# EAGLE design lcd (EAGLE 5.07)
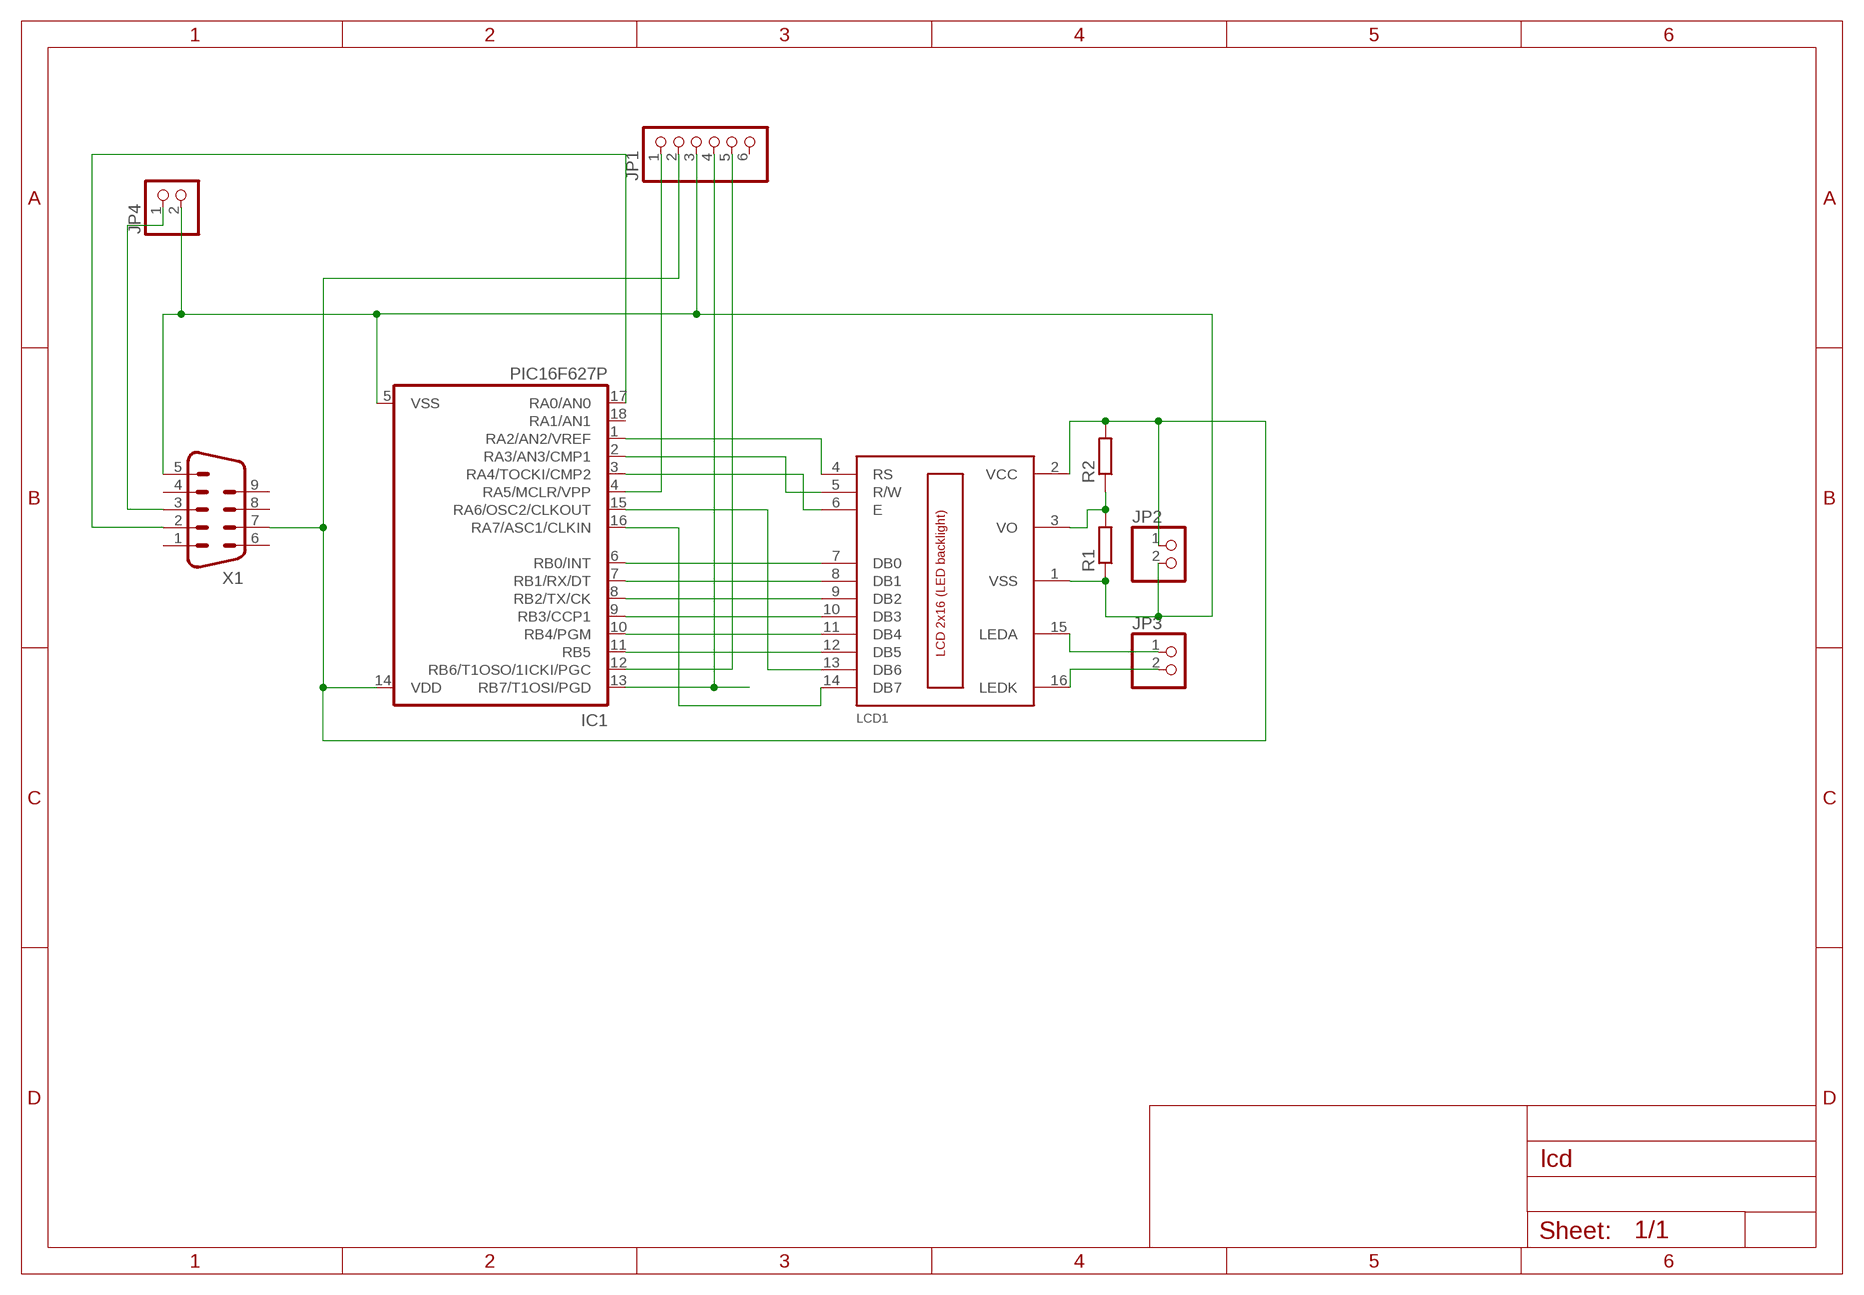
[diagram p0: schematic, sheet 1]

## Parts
IC1  PIC16F627P  [DIL18]
JP1  PINHD-1X6  [1X06]
JP2  PINHD-1X2  [1X02]
JP3  PINHD-1X2  [1X02]
JP4  PINHD-1X2  [1X02]
LCD1  LCD_2X16  [HY-1602F]
R1  R-EU_0204/5  [0204/5]
R2  R-EU_0204/2V  [0204V]
X1  M09HP  [M09HP]

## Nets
N$1: IC1.4(RA5/MCLR/VPP) JP1.1
N$2: IC1.12(RB6/T1OSO/1ICKI/PGC) JP1.5
N$3: IC1.13(RB7/T1OSI/PGD) JP1.4
N$4: IC1.15(RA6/OSC2/CLKOUT) LCD1.13(DB6)
N$5: IC1.16(RA7/ASC1/CLKIN) LCD1.14(DB7)
N$6: IC1.11(RB5) LCD1.12(DB5)
N$7: IC1.10(RB4/PGM) LCD1.11(DB4)
N$8: IC1.9(RB3/CCP1) LCD1.10(DB3)
N$9: IC1.8(RB2/TX/CK) LCD1.9(DB2)
N$10: IC1.7(RB1/RX/DT) LCD1.8(DB1)
N$11: IC1.6(RB0/INT) LCD1.7(DB0)
N$12: IC1.3(RA4/TOCKI/CMP2) LCD1.6(E)
N$13: IC1.1(RA2/AN2/VREF) LCD1.4(RS)
N$14: IC1.2(RA3/AN3/CMP1) LCD1.5(R/W)
N$15: JP3.2 LCD1.16(LEDK)
N$16: JP3.1 LCD1.15(LEDA)
N$18: JP4.1 X1.3
N$19: LCD1.3(VO) R1.2 R2.1
N$20: IC1.17(RA0/AN0) X1.2
VDD: IC1.14(VDD) JP1.2 JP2.1 LCD1.2(VCC) R2.2 X1.7
VSS: IC1.5(VSS) JP1.3 JP2.2 JP4.2 LCD1.1(VSS) R1.1 X1.5
Unconnected: IC1.18(RA1/AN1) JP1.6 X1.1 X1.4 X1.6 X1.8 X1.9

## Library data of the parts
IC1 = microchip:PIC16*F62: FLASH-Based 8-Bit CMOS Microcontroller Source: http://ww1.microchip.com/downloads/en/DeviceDoc/40300C.pdf
JP1 = pinhead:PINHD-1X6: PIN HEADER
JP2 JP3 = pinhead:PINHD-1X2: PIN HEADER
JP4 = pinhead(2):PINHD-1X2: PIN HEADER
LCD1 = lcd_2x16_led_backlight:LCD_2X16
R1 R2 = rcl:R-EU_: RESISTOR, European symbol
X1 = con-subd:M09: SUB-D

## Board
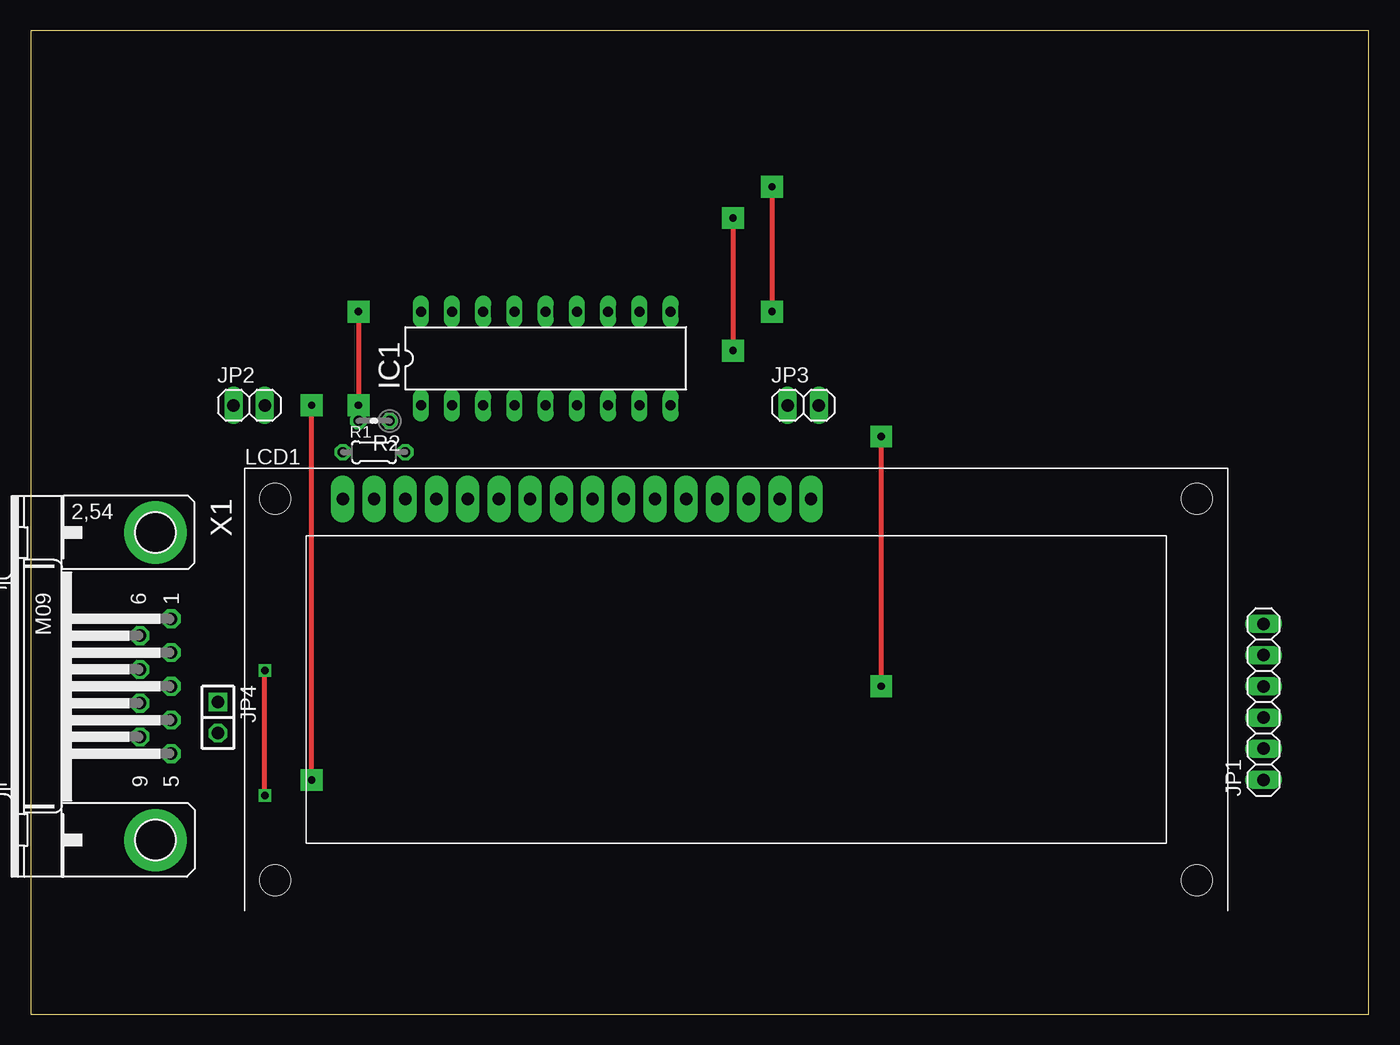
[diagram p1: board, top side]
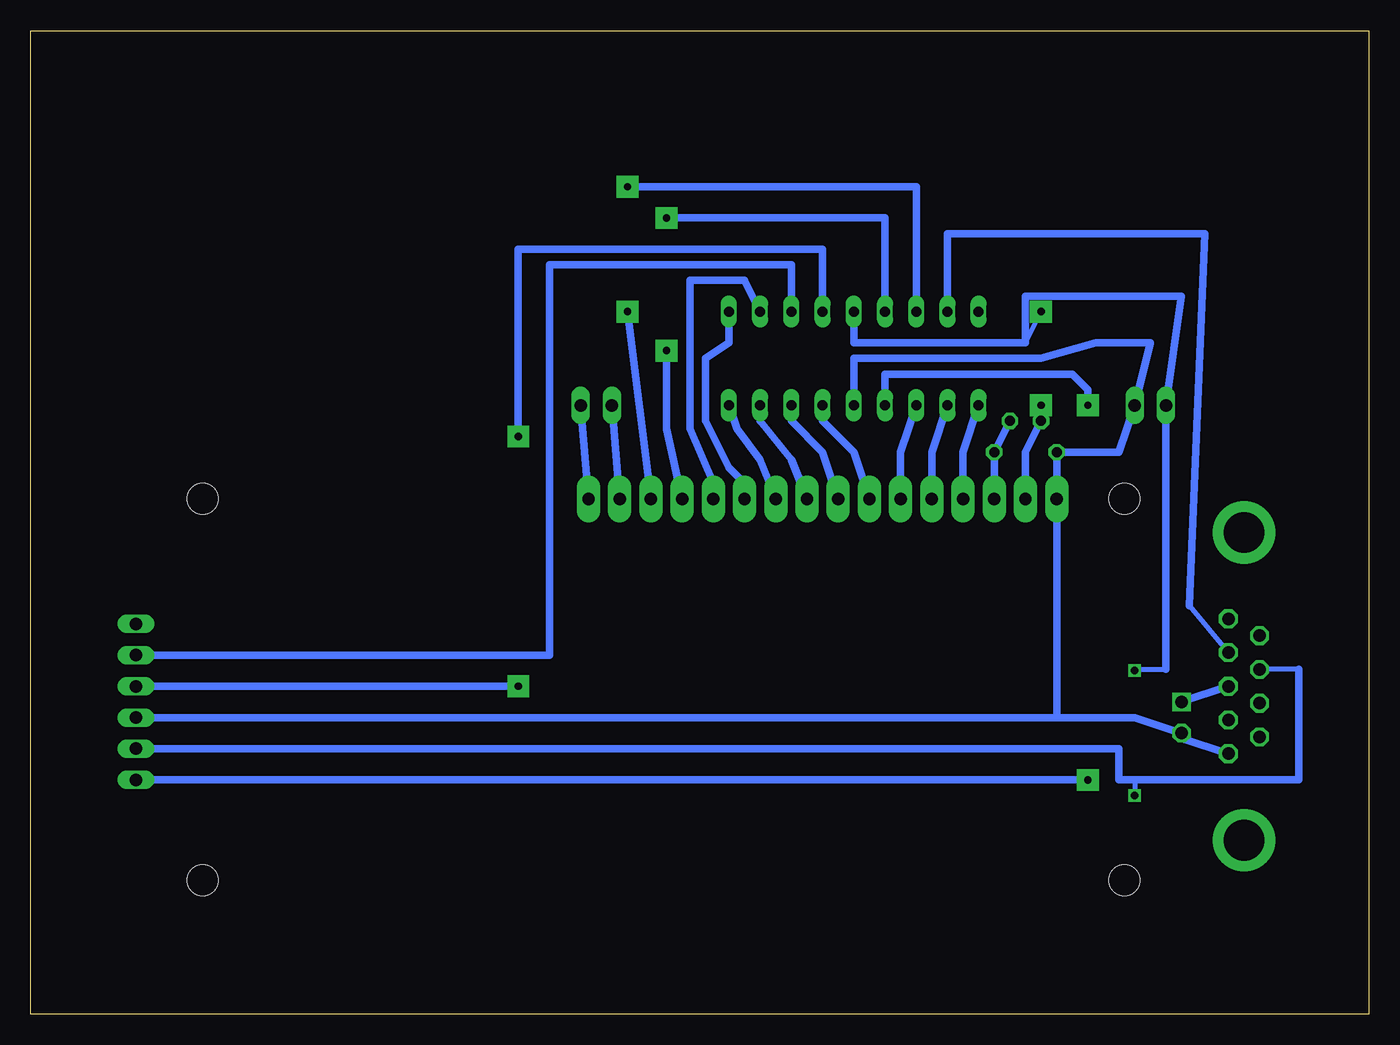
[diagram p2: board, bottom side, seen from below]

Size 108.89 x 80 mm. Coordinates in mm from the lower left corner, seen from the top.
Outline: 0,0 108.89,0 108.89,80 0,80 0,0
Copper layers (1*16): Top 0.035mm / dielectric 1.5mm / Bottom 0.035mm
Design rules "default": minimum track width 10mil, minimum drill 24mil, track to track 8mil, track to pad 8mil, pad to pad 8mil, via to via 8mil, smd to smd 8mil, copper to edge 40mil, drill to drill 8mil, minimum pad ring 10mil, minimum via ring 8mil, stop-mask expansion 4mil, vias tented up to drill 0mil, thermal gap 10mil

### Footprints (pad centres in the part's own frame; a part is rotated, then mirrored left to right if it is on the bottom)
DIL18 = drill 0.813 long: 1 -10.16,-3.81; 2 -7.62,-3.81; 3 -5.08,-3.81; 4 -2.54,-3.81; 5 0,-3.81; 6 2.54,-3.81; 7 5.08,-3.81; 8 7.62,-3.81; 9 10.16,-3.81; 10 10.16,3.81; 11 7.62,3.81; 12 5.08,3.81; 13 2.54,3.81; 14 0,3.81; 15 -2.54,3.81; 16 -5.08,3.81; 17 -7.62,3.81; 18 -10.16,3.81
1X06 = drill 1.016 long: 1 -6.35,0; 2 -3.81,0; 3 -1.27,0; 4 1.27,0; 5 3.81,0; 6 6.35,0
1X02 = drill 1.016 long: 1 -1.27,0; 2 1.27,0
1X02' = drill 1.016 square: 1 -1.27,0 | drill 1.016 octagon: 2 1.27,0
HY-1602F = drill 1 pad 1.93 long: 1 2.54,0; 2 5.08,0; 3 7.62,0; 4 10.16,0; 5 12.7,0; 6 15.24,0; 7 17.78,0; 8 20.32,0; 9 22.86,0; 10 25.4,0; 11 27.94,0; 12 30.48,0; 13 33.02,0; 14 35.56,0; 15 38.1,0; 16 40.64,0 | hole 2.5: -2.96,0; 72.04,0; -2.96,-31; 72.04,-31
0204/5 = drill 0.813 octagon: 1 -2.54,0; 2 2.54,0
0204V = drill 0.813 octagon: 1 -1.27,0; 2 1.27,0
M09HP = drill 1.016 octagon: 1 -5.486,1.27; 2 -2.743,1.27; 3 0,1.27; 4 2.743,1.27; 5 5.486,1.27; 6 -4.115,-1.27; 7 -1.372,-1.27; 8 1.372,-1.27; 9 4.115,-1.27 | drill 3.302 pad 5.08 round: G1 -12.522,0; G2 12.522,0

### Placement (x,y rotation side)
IC1  41.91,53.34 0 top
JP1  100.33,25.4 90 top
JP2  17.78,49.53 0 top
JP3  62.87,49.53 0 top
JP4  [1X02']  15.24,24.13 270 top
LCD1  22.86,41.91 0 top
R1  27.94,45.72 0 top
R2  27.94,48.26 180 top
X1  10.16,26.67 270 top

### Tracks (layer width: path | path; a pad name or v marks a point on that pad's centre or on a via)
N$1  (via drill 0.6 pad 1.78)
  Top 0.406: v22.86,19.05 v22.86,49.53
  Bottom 0.61: IC1.4 39.37,52.07 24.13,52.07 22.86,50.8 v22.86,49.53 | v22.86,19.05 JP1.1
N$2
  Bottom 0.61: JP1.5 66.67,29.21 66.67,60.96 46.99,60.96 IC1.12
N$3  (via drill 0.6 pad 1.78)
  Top 0.406: v69.22,26.67 v69.22,46.99
  Bottom 0.61: IC1.13 44.45,62.23 69.22,62.23 v69.22,46.99 | v69.22,26.67 JP1.4
N$4  (via drill 0.6 pad 1.78)
  Top 0.406: v57.15,64.77 v57.15,53.98
  Bottom 0.61: IC1.15 39.37,64.77 v57.15,64.77 | v57.15,53.98 57.15,47.62 LCD1.13
N$5  (via drill 0.6 pad 1.78)
  Top 0.406: v60.33,67.31 v60.33,57.15
  Bottom 0.61: IC1.16 36.83,67.31 v60.33,67.31 | v60.33,57.15 LCD1.14
N$6
  Bottom 0.254: LCD1.12 53.34,43.18
  Bottom 0.61: IC1.11 50.8,59.69 55.24,59.69 55.24,47.62 53.34,43.18
N$7
  Bottom 0.254: LCD1.11 50.8,43.18
  Bottom 0.61: IC1.10 52.07,54.61 53.98,53.34 53.98,48.26 52.07,44.45 50.8,43.18
N$8
  Bottom 0.61: LCD1.10 49.53,45.09 51.44,47.62 IC1.9
N$9
  Bottom 0.61: LCD1.9 46.99,45.09 49.53,48.26 IC1.8
N$10
  Bottom 0.61: LCD1.8 44.45,45.72 46.99,48.26 IC1.7
N$11
  Bottom 0.61: LCD1.7 41.91,45.72 44.45,48.26 IC1.6
N$12
  Bottom 0.61: IC1.3 38.1,45.72 LCD1.6
N$13
  Bottom 0.61: IC1.1 33.02,45.72 LCD1.4
N$14
  Bottom 0.61: IC1.2 35.56,45.72 LCD1.5
N$15
  Bottom 0.61: LCD1.16 JP3.2
N$16
  Bottom 0.61: LCD1.15 JP3.1
N$18
  Bottom 0.61: X1.3 JP4.1
N$19
  Bottom 0.61: R2.1 R1.2 LCD1.3
N$20
  Bottom 0.406: 14.61,33.22 X1.2
  Bottom 0.61: 14.61,33.22 13.34,63.5 34.29,63.5 IC1.17
VDD  (via drill 0.6, 0.6 pad 1.78)
  Top 0.406: v26.67,57.15 v26.67,49.53 | v19.05,17.78 v19.05,27.94
  Bottom 0.406: 5.71,28.04 X1.7 | v26.67,49.53 R2.2 | 27.94,54.61 v26.67,57.15 | 16.51,28.07 19.05,28.07 v19.05,27.94 | 19.05,19.05 v19.05,17.78
  Bottom 0.61: IC1.14 41.91,54.61 27.94,54.61 27.94,58.42 15.24,58.42 JP2.1 16.51,28.07 | JP1.2 20.32,21.59 20.32,19.05 19.05,19.05 5.71,19.05 5.71,28.04 | LCD1.2 27.94,45.72 R2.2
VSS
  Bottom 0.406: 15.24,22.45 JP4.2
  Bottom 0.61: X1.5 15.24,22.45 | 25.4,24.13 19.05,24.13 JP4.2 | 25.4,24.13 JP1.3 | 25.4,24.13 LCD1.1 R1.1 20.32,45.72 JP2.2 17.78,54.61 22.23,54.61 26.67,53.34 41.91,53.34 IC1.5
